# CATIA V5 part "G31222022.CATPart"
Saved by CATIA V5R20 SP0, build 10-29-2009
Part number: G31222022
Revision: 10
Definition: design
Nomenclature: G31222022
Source: made
Description: NOT SPECIFIED
Bounding box of the stored display mesh (mm): x -8 to 22, y -17.322 to 17.322, z -17.5 to 17.5
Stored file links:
  C:\Users\Raffaele\Desktop\3D X SITO CF\BOLEX\23-BUSH REF 312\G31222022.CATPart

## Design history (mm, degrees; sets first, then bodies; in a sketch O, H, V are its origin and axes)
Body1 "MANIFOLD_SOLID_BREP #3911" (main body)
  Solid1: solid without history
Body2 "MANIFOLD_SOLID_BREP #4058"
  Solid2: solid without history
Body3 "MANIFOLD_SOLID_BREP #4205"
  Solid3: solid without history
Body4 "MANIFOLD_SOLID_BREP #4352"
  Solid4: solid without history
Body5 "MANIFOLD_SOLID_BREP #4499"
  Solid5: solid without history
Body6 "MANIFOLD_SOLID_BREP #4648"
  Solid6: solid without history
Body7 "MANIFOLD_SOLID_BREP #4797"
  Solid7: solid without history
Body8 "MANIFOLD_SOLID_BREP #4946"
  Solid8: solid without history
Body9 "MANIFOLD_SOLID_BREP #5095"
  Solid9: solid without history
Body10 "MANIFOLD_SOLID_BREP #5244"
  Solid10: solid without history
Body11 "MANIFOLD_SOLID_BREP #5393"
  Solid11: solid without history
Body12 "MANIFOLD_SOLID_BREP #5542"
  Solid12: solid without history
Body13 "MANIFOLD_SOLID_BREP #5691"
  Solid13: solid without history
Body14 "MANIFOLD_SOLID_BREP #5840"
  Solid14: solid without history
Body15 "MANIFOLD_SOLID_BREP #5989"
  Solid15: solid without history
Body16 "MANIFOLD_SOLID_BREP #6138"
  Solid16: solid without history
Body17 "MANIFOLD_SOLID_BREP #6287"
  Solid17: solid without history
Body18 "MANIFOLD_SOLID_BREP #6436"
  Solid18: solid without history
Body19 "MANIFOLD_SOLID_BREP #6585"
  Solid19: solid without history
Body20 "MANIFOLD_SOLID_BREP #6734"
  Solid20: solid without history
Body21 "MANIFOLD_SOLID_BREP #6883"
  Solid21: solid without history
Body22 "MANIFOLD_SOLID_BREP #7032"
  Solid22: solid without history
Body23 "MANIFOLD_SOLID_BREP #7181"
  Solid23: solid without history
Body24 "MANIFOLD_SOLID_BREP #7330"
  Solid24: solid without history
Body25 "MANIFOLD_SOLID_BREP #7479"
  Solid25: solid without history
